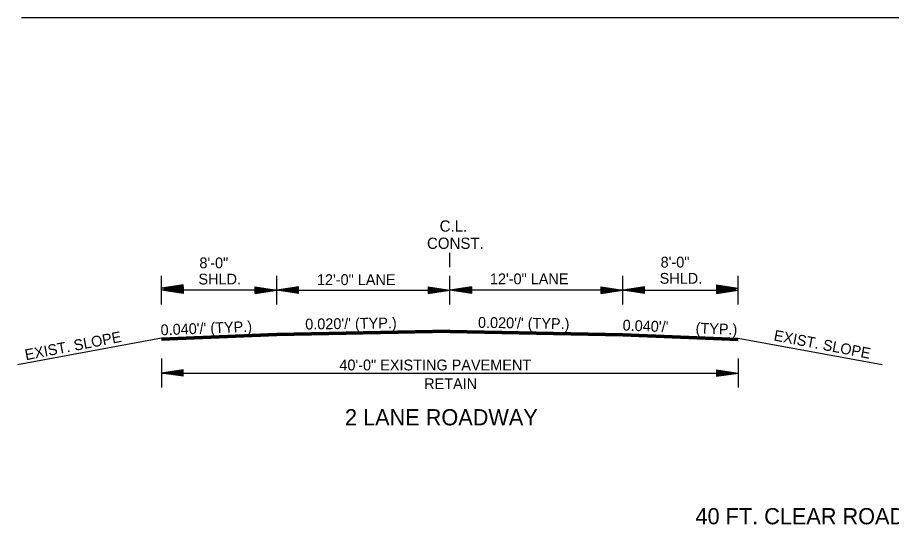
# Model space of a CAD drawing. Extents: x 545241 to 1930787, y -1971772 to 596640.
# Drawn here: x 546740 to 547347, y -1959957 to -1959605 of the extents above; entities that cross this region are included whole.
import ezdxf

# ---------------------------------------------------------------- set-up
doc = ezdxf.new("R2010")
doc.units = 0
doc.layers.add('R_Border', color=7, linetype='Continuous')
doc.layers.add('R_Draft', color=7, linetype='Continuous')

msp = doc.modelspace()

# ---------------------------------------------------------------- linework, layer by layer
at = {"layer": 'R_Border'}
for p, q in [((546742.77, -1959605.24), (547770.72, -1959605.24)), ((546920.03, -1959824.55), (546840.03, -1959827.75)), ((547160.03, -1959824.55), (547240.03, -1959827.75)), ((546920.03, -1959824.85), (546840.03, -1959828.05)), ((546920.03, -1959825.15), (546840.03, -1959828.35)), ((546920.03, -1959825.45), (546840.03, -1959828.65)), ((546920.03, -1959825.75), (546840.03, -1959828.95)), ((546920.03, -1959826.05), (546840.03, -1959829.25)), ((546920.03, -1959826.22), (546840.03, -1959829.42)), ((547160.03, -1959824.85), (547240.03, -1959828.05)), ((547160.03, -1959825.15), (547240.03, -1959828.35)), ((547160.03, -1959825.45), (547240.03, -1959828.65)), ((547160.03, -1959825.75), (547240.03, -1959828.95)), ((547160.03, -1959826.05), (547240.03, -1959829.25)), ((547160.03, -1959826.22), (547240.03, -1959829.42))]:
    msp.add_line(p, q, dxfattribs=at)
at = {"layer": 'R_Draft'}
for p, q in [((547040.03, -1959778.5), (547040.03, -1959768.5)), ((546840.03, -1959804.54), (546840.03, -1959784.54)), ((546920.03, -1959804.54), (546920.03, -1959784.65)), ((547040.03, -1959804.54), (547040.03, -1959784.65)), ((547160.03, -1959804.54), (547160.03, -1959784.65)), ((547240.03, -1959804.54), (547240.03, -1959784.54)), ((546855.03, -1959790.9), (546840.03, -1959793.15)), ((546855.03, -1959792.29), (546840.03, -1959794.54)), ((546855.03, -1959795.4), (546840.03, -1959793.15)), ((546855.03, -1959791.28), (546842.54, -1959793.15)), ((546855.03, -1959792.67), (546842.54, -1959794.54)), ((546855.03, -1959795.03), (546842.54, -1959793.15)), ((546855.03, -1959791.66), (546845.12, -1959793.15)), ((546855.03, -1959793.05), (546845.12, -1959794.54)), ((546855.03, -1959794.64), (546845.12, -1959793.15)), ((546855.03, -1959792.03), (546847.62, -1959793.15)), ((546855.03, -1959794.27), (546847.62, -1959793.15)), ((546855.03, -1959793.42), (546847.62, -1959794.54)), ((546855.03, -1959792.42), (546850.16, -1959793.15)), ((546855.03, -1959793.88), (546850.16, -1959793.15)), ((546855.03, -1959793.81), (546850.16, -1959794.54)), ((546855.03, -1959792.8), (546852.66, -1959793.15)), ((546855.03, -1959793.5), (546852.66, -1959793.15)), ((546855.03, -1959794.19), (546852.66, -1959794.54)), ((546855.03, -1959795.4), (546855.03, -1959790.9)), ((546855.03, -1959792.29), (546855.03, -1959796.79)), ((546905.03, -1959792.29), (546920.03, -1959794.54)), ((546905.03, -1959796.79), (546905.03, -1959792.29)), ((546905.03, -1959792.67), (546917.53, -1959794.54)), ((546905.03, -1959793.05), (546914.95, -1959794.54)), ((546905.03, -1959793.42), (546912.45, -1959794.54)), ((546905.03, -1959793.81), (546909.91, -1959794.54)), ((546905.03, -1959794.19), (546907.4, -1959794.54)), ((546935.03, -1959792.29), (546920.03, -1959794.54)), ((546935.03, -1959792.67), (546922.54, -1959794.54)), ((546935.03, -1959793.05), (546925.12, -1959794.54)), ((546935.03, -1959793.42), (546927.62, -1959794.54)), ((546935.03, -1959793.81), (546930.16, -1959794.54)), ((546935.03, -1959794.19), (546932.66, -1959794.54)), ((546935.03, -1959796.79), (546935.03, -1959792.29)), ((547025.03, -1959792.29), (547040.03, -1959794.54)), ((547025.03, -1959792.29), (547025.03, -1959796.79)), ((547025.03, -1959792.67), (547037.53, -1959794.54)), ((547025.03, -1959793.05), (547034.95, -1959794.54)), ((547025.03, -1959793.42), (547032.45, -1959794.54)), ((547025.03, -1959793.81), (547029.91, -1959794.54)), ((547025.03, -1959794.19), (547027.4, -1959794.54)), ((547055.03, -1959792.29), (547040.03, -1959794.54)), ((547055.03, -1959792.67), (547042.54, -1959794.54)), ((547055.03, -1959793.05), (547045.12, -1959794.54)), ((547055.03, -1959793.42), (547047.62, -1959794.54)), ((547055.03, -1959793.81), (547050.16, -1959794.54)), ((547055.03, -1959794.19), (547052.66, -1959794.54)), ((547055.03, -1959792.29), (547055.03, -1959796.79)), ((547145.03, -1959792.29), (547160.03, -1959794.54)), ((547145.03, -1959796.79), (547145.03, -1959792.29)), ((547145.03, -1959792.67), (547157.53, -1959794.54)), ((547145.03, -1959793.05), (547154.95, -1959794.54)), ((547145.03, -1959793.42), (547152.45, -1959794.54)), ((547145.03, -1959793.81), (547149.91, -1959794.54)), ((547145.03, -1959794.19), (547147.4, -1959794.54)), ((547175.03, -1959792.29), (547160.03, -1959794.54)), ((547175.03, -1959792.67), (547162.54, -1959794.54)), ((547175.03, -1959793.05), (547165.12, -1959794.54)), ((547175.03, -1959793.42), (547167.62, -1959794.54)), ((547175.03, -1959793.81), (547170.16, -1959794.54)), ((547175.03, -1959794.19), (547172.66, -1959794.54)), ((547175.03, -1959796.79), (547175.03, -1959792.29)), ((547225.03, -1959790.9), (547240.03, -1959793.15)), ((547225.03, -1959790.9), (547225.03, -1959795.4)), ((547225.03, -1959791.28), (547237.53, -1959793.15)), ((547225.03, -1959791.66), (547234.95, -1959793.15)), ((547225.03, -1959792.03), (547232.45, -1959793.15)), ((547225.03, -1959792.29), (547240.03, -1959794.54)), ((547225.03, -1959792.29), (547225.03, -1959796.79)), ((547225.03, -1959792.42), (547229.91, -1959793.15)), ((547225.03, -1959792.67), (547237.53, -1959794.54)), ((547225.03, -1959792.8), (547227.4, -1959793.15)), ((547225.03, -1959793.05), (547234.95, -1959794.54)), ((547225.03, -1959795.4), (547240.03, -1959793.15)), ((547225.03, -1959793.89), (547229.91, -1959793.15)), ((547225.03, -1959794.64), (547234.95, -1959793.15)), ((547225.03, -1959795.03), (547237.53, -1959793.15)), ((547225.03, -1959794.27), (547232.45, -1959793.15)), ((547225.03, -1959793.5), (547227.4, -1959793.15)), ((547225.03, -1959793.42), (547232.45, -1959794.54)), ((547225.03, -1959793.81), (547229.91, -1959794.54)), ((547225.03, -1959794.19), (547227.4, -1959794.54)), ((546920.03, -1959794.54), (546840.03, -1959794.54)), ((546855.03, -1959796.79), (546840.03, -1959794.54)), ((546855.03, -1959796.42), (546842.54, -1959794.54)), ((546855.03, -1959796.03), (546845.12, -1959794.54)), ((546855.03, -1959795.66), (546847.62, -1959794.54)), ((546855.03, -1959795.28), (546850.16, -1959794.54)), ((546855.03, -1959794.89), (546852.66, -1959794.54)), ((546905.03, -1959796.79), (546920.03, -1959794.54)), ((546905.03, -1959795.27), (546909.91, -1959794.54)), ((546905.03, -1959796.03), (546914.95, -1959794.54)), ((546905.03, -1959796.42), (546917.53, -1959794.54)), ((546905.03, -1959795.66), (546912.45, -1959794.54)), ((546905.03, -1959794.89), (546907.4, -1959794.54)), ((546935.03, -1959796.79), (546920.03, -1959794.54)), ((546920.03, -1959794.54), (547040.03, -1959794.54)), ((546935.03, -1959796.42), (546922.54, -1959794.54)), ((546935.03, -1959796.03), (546925.12, -1959794.54)), ((546935.03, -1959795.66), (546927.62, -1959794.54)), ((546935.03, -1959795.27), (546930.16, -1959794.54)), ((546935.03, -1959794.89), (546932.66, -1959794.54)), ((547025.03, -1959796.79), (547040.03, -1959794.54)), ((547025.03, -1959795.28), (547029.91, -1959794.54)), ((547025.03, -1959796.03), (547034.95, -1959794.54)), ((547025.03, -1959796.42), (547037.53, -1959794.54)), ((547025.03, -1959795.66), (547032.45, -1959794.54)), ((547025.03, -1959794.89), (547027.4, -1959794.54)), ((547160.03, -1959794.54), (547040.03, -1959794.54)), ((547055.03, -1959796.79), (547040.03, -1959794.54)), ((547055.03, -1959796.42), (547042.54, -1959794.54)), ((547055.03, -1959796.03), (547045.12, -1959794.54)), ((547055.03, -1959795.66), (547047.62, -1959794.54)), ((547055.03, -1959795.28), (547050.16, -1959794.54)), ((547055.03, -1959794.89), (547052.66, -1959794.54)), ((547145.03, -1959796.79), (547160.03, -1959794.54)), ((547145.03, -1959795.27), (547149.91, -1959794.54)), ((547145.03, -1959796.03), (547154.95, -1959794.54)), ((547145.03, -1959796.42), (547157.53, -1959794.54)), ((547145.03, -1959795.66), (547152.45, -1959794.54)), ((547145.03, -1959794.89), (547147.4, -1959794.54)), ((547160.03, -1959794.54), (547240.03, -1959794.54)), ((547175.03, -1959796.79), (547160.03, -1959794.54)), ((547175.03, -1959796.42), (547162.54, -1959794.54)), ((547175.03, -1959796.03), (547165.12, -1959794.54)), ((547175.03, -1959795.66), (547167.62, -1959794.54)), ((547175.03, -1959795.27), (547170.16, -1959794.54)), ((547175.03, -1959794.89), (547172.66, -1959794.54)), ((547225.03, -1959796.79), (547240.03, -1959794.54)), ((547225.03, -1959795.28), (547229.91, -1959794.54)), ((547225.03, -1959796.03), (547234.95, -1959794.54)), ((547225.03, -1959796.42), (547237.53, -1959794.54)), ((547225.03, -1959795.66), (547232.45, -1959794.54)), ((547225.03, -1959794.89), (547227.4, -1959794.54)), ((547040.03, -1959822.15), (546920.03, -1959824.55)), ((547040.03, -1959822.45), (546920.03, -1959824.85)), ((547040.03, -1959822.75), (546920.03, -1959825.15)), ((547040.05, -1959823.05), (546920.03, -1959825.45)), ((547040.06, -1959823.35), (546920.03, -1959825.75)), ((547040.06, -1959823.65), (546920.03, -1959826.05)), ((547040.07, -1959823.82), (546920.03, -1959826.22)), ((547040, -1959823.65), (547160.03, -1959826.05)), ((547040, -1959823.82), (547160.03, -1959826.22)), ((547040.01, -1959823.35), (547160.03, -1959825.75)), ((547040.02, -1959822.75), (547160.03, -1959825.15)), ((547040.02, -1959823.05), (547160.03, -1959825.45)), ((547040.03, -1959822.15), (547160.03, -1959824.55)), ((547040.03, -1959822.45), (547160.03, -1959824.85)), ((546840.03, -1959827.75), (546740.06, -1959846.4)), ((547240.03, -1959827.75), (547340.1, -1959846.12)), ((546840.03, -1959842.01), (546840.03, -1959862.01)), ((547240.03, -1959842.01), (547240.03, -1959862.01)), ((546855.03, -1959849.76), (546840.03, -1959852.01)), ((546840.03, -1959852.01), (547240.03, -1959852.01)), ((546855.03, -1959854.26), (546840.03, -1959852.01)), ((546855.03, -1959850.13), (546842.54, -1959852.01)), ((546855.03, -1959853.88), (546842.54, -1959852.01)), ((546855.03, -1959850.51), (546845.12, -1959852.01)), ((546855.03, -1959853.5), (546845.12, -1959852.01)), ((546855.03, -1959850.89), (546847.62, -1959852.01)), ((546855.03, -1959853.12), (546847.62, -1959852.01)), ((546855.03, -1959851.27), (546850.16, -1959852.01)), ((546855.03, -1959852.73), (546850.16, -1959852.01)), ((546855.03, -1959851.65), (546852.66, -1959852.01)), ((546855.03, -1959852.36), (546852.66, -1959852.01)), ((546855.03, -1959854.26), (546855.03, -1959849.76)), ((547225.03, -1959849.76), (547240.03, -1959852.01)), ((547225.03, -1959849.76), (547225.03, -1959854.26)), ((547225.03, -1959850.13), (547237.53, -1959852.01)), ((547225.03, -1959850.51), (547234.95, -1959852.01)), ((547225.03, -1959850.89), (547232.45, -1959852.01)), ((547225.03, -1959851.28), (547229.91, -1959852.01)), ((547225.03, -1959851.65), (547227.4, -1959852.01)), ((547225.03, -1959854.26), (547240.03, -1959852.01)), ((547225.03, -1959852.74), (547229.91, -1959852.01)), ((547225.03, -1959853.5), (547234.95, -1959852.01)), ((547225.03, -1959853.88), (547237.53, -1959852.01)), ((547225.03, -1959853.12), (547232.45, -1959852.01)), ((547225.03, -1959852.36), (547227.4, -1959852.01))]:
    msp.add_line(p, q, dxfattribs=at)

# ---------------------------------------------------------------- texts
at = {"layer": 'R_Border'}
msp.add_text('RETAIN', height=7.5, dxfattribs=at).set_placement((547022.23, -1959863.17))
at = {"layer": 'R_Draft'}
for s, height, p in [('C.L.', 7.8, (547032.98, -1959753.88)), ('CONST.', 7.8, (547024.2, -1959765.84)), ('8\'-0"', 7.5, (546866.3, -1959779.3)), ('8\'-0"', 7.5, (547186.3, -1959778.78)), ('SHLD.', 7.5, (546865.62, -1959790.55)), ('12\'-0" LANE', 7.5, (546947.85, -1959790.94)), ('12\'-0" LANE', 7.5, (547067.85, -1959790.41)), ('SHLD.', 7.5, (547185.62, -1959790.03)), ('40\'-0" EXISTING PAVEMENT', 7.5, (546963.41, -1959850.17)), ('2 LANE ROADWAY', 11.25, (546967.31, -1959888.32)), ('40 FT. CLEAR ROADWAY BRIDGE - POLYMER OVERLAY', 11.25, (547210.51, -1959956.98))]:
    msp.add_text(s, height=height, dxfattribs=at).set_placement(p)
for s, rotation, p in [("0.040'/' (TYP.)", 2.29061, (546839.52, -1959825.85)), ("0.020'/' (TYP.)", 0.87191, (546939.77, -1959821.83)), ("0.020'/' (TYP.)", 359.12809, (547059.53, -1959820.6)), ("0.040'/' ", 357.70939, (547159.82, -1959822.44)), ('(TYP.)', 357.70939, (547210.45, -1959824.46)), ('EXIST. SLOPE', 10.88286, (546745.94, -1959843.14)), ('EXIST. SLOPE', 349.11714, (547264.41, -1959829.34))]:
    msp.add_text(s, height=7.5, rotation=rotation, dxfattribs=at).set_placement(p)

doc.saveas('drawing.dxf')
